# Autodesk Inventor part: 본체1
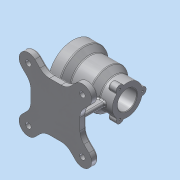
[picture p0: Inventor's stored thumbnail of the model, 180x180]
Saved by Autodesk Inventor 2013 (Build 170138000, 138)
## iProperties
Created: 2017-03
Part Number: 본체1
Material: 알루미늄 6061
Document SubType Name: Modeling
Designer: dgall
Density: 2.71 g/cm^3
Mass: 1008.06 g
Surface Area: 842.101 cm^2
Volume: 371.979 cm^3
Author: dgall
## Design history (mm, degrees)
sketch "스케치1"
  geometry: L1 (0, 0)-(100, 0); L2 (0, 0)-(0, 45); L3 (0, 45)-(20, 45); L4 (20, 45)-(31, 36); L5 (31, 36)-(65, 36); L6 (77, 27.5)-(100, 27.5); L7 (100, 27.5)-(100, 0); L8 (77, 27.5)-(65, 36)
  constraints: 16 end point, 2 perpendicular, 1 horizontal, 1 parallel, 1 vertical
  dimensions: "d0" = 100 distance of L1.start L1.end; "d1" = 20 distance of L2.end L3.end; "d2" = 31 distance from line of L4.end L2; "d5" = 65 distance from line of L2 L5.end; "d6" = 90 diameter of L3 L1; "d7" = 55 diameter of L6 L1; "d8" = 72 diameter of L4.end L1; "d146" = 23 distance from line of L6.start L7
revolve "회전1" sketch "스케치1" stored, may be unused: angle "d10" = 90 deg
node "작업축1"
node "작업 평면2"
  node "작업 평면1"
sketch "스케치2"
  geometry: L1 (6.5, -45)-(-83.5, -45); L2 (-83.5, -45)-(-83.5, 45); L3 (-83.5, 45)-(6.5, 45); L4 (6.5, 45)-(6.5, -45); L5 (6.5, -45)-(-83.5, 45); L6 (-83.5, -45)-(6.5, 45); L7 (-88.5, -45)-(-88.5, 45) reference; L8 (11.5, -27.5)-(11.5, 27.5) reference; 4 further points
  constraints: 12 end point, 4 midpoint, 2 parallel, 1 horizontal, 1 horizontal alignment, 1 perpendicular
  dimensions: "d13" = 90 distance of L2.end L3.end; "d14" = 90 distance of L1.end L2.end; "d15" = 50 distance from line of point (-38.5, 0) L8
extrude "돌출1" join sketch "스케치2" distance "d25" = 12; taper "d26" = 0 deg
sketch "스케치3"
  geometry: L1 (6.5, -45)-(-83.5, -45) reference; L2 (6.5, 45)-(6.5, -45) reference; L3 (-83.5, 45)-(6.5, 45) reference; L4 (-83.5, -45)-(-83.5, 45) reference; L5 (-38.5, 45)-(-38.5, -45); L6 (-83.5, 0)-(6.5, 0); L7 (-87.997, 49.497)-(10.997, -49.497); L8 (10.997, 49.497)-(-87.997, -49.497); L9 (-100.018, 37.477)-(-83.5, 20.958); L10 (-75.977, 61.518)-(-59.458, 45); L11 (23.018, -37.477)-(6.5, -20.958); L12 (-1.023, -61.518)-(-17.542, -45); L13 (23.018, 37.477)-(6.5, 20.958); L14 (-1.023, 61.518)-(-17.542, 45); L15 (-100.018, -37.477)-(-83.5, -20.958); L16 (-75.977, -61.518)-(-59.458, -45); A1 r 17 centre (-87.997, 49.497) between (-100.018, 37.477) and (-75.977, 61.518); A2 r 17 centre (10.997, 49.497) between (23.018, 37.477) and (-1.023, 61.518); A3 r 17 centre (-87.997, -49.497) between (-100.018, -37.477) and (-75.977, -61.518); A4 r 17 centre (10.997, -49.497) between (23.018, -37.477) and (-1.023, -61.518); 7 further points
  constraints: 24 end point, 10 midpoint, 8 point on circle, 8 point on line, 8 tangent, 6 equal length, 4 centre point, 4 horizontal alignment, 4 perpendicular, 2 coincident, 2 vertical alignment, 1 equal radius
  dimensions: "d38" = 70 distance of point (-38.5, 0) L7.start; "d39" = 45 deg angle of L5 L7; "d40" = 34 diameter of A2; "d41" = 34 diameter of A4; "d42" = 34 diameter of A3; "d43" = 70 distance of point (-38.5, 0) L7.end
extrude "돌출2" join sketch "스케치3" distance "d44" = 12; taper "d45" = 0 deg
node "작업 평면3"
sketch "스케치4"
  geometry: L1 (-75.977, -70)-(-104.997, -70) reference; L2 (11.5, -27.5)-(11.5, 27.5) reference; L3 (-88.5, -45)-(-88.5, 45) reference; L4 (-59.458, -70)-(-75.977, -70) reference; L5 (-17.542, -70)-(-59.458, -70) reference; L6 (-1.023, -70)-(-17.542, -70) reference; L7 (6.5, -70)-(23.018, -70) reference; L8 (27.997, -70)-(-1.023, -70) reference; L9 (-75.5, -70)-(-75.5, -3.971); L10 (-75.5, -3.971)-(-1.5, -3.971); L11 (-1.5, -3.971)-(-1.5, -70); L12 (-75.5, -70)-(-1.5, -70); 4 further points
  constraints: 8 end point, 4 perpendicular, 3 midpoint, 2 point on line, 1 coincident, 1 vertical alignment
  dimensions: "d52" = 74 distance of L9.end L10.end; "d55" = 66.02908 distance between parallel lines of L5 L10
extrude "돌출3" join sketch "스케치4" stored distance "d56" = 8; taper "d57" = 0 deg
node "작업 평면4"
sketch "스케치5"
  geometry: L1 (20.958, -82)-(37.477, -82) reference; L2 (20.958, -70)-(20.958, -82) reference; L3 (37.477, -70)-(20.958, -70) reference; L4 (37.477, -82)-(37.477, -70) reference; L5 (-4, -44.822)-(-4, -35.777) reference; L6 (4, -35.777)-(4, -44.822) reference; L7 (-13.944, -7.299)-(-25, -70); L8 (-25, -70)-(25, -70); L9 (25, -70)-(13.944, -7.299); L10 (13.944, -7.299)-(-13.944, -7.299); L11 (-20.958, -70)-(-37.477, -70) reference; A1 r 45 centre (0, 0) between (4, -44.822) and (-4, -44.822) reference; A2 r 36 centre (0, 0) between (4, -35.777) and (-4, -35.777) reference; A3 r 45 centre (0, 0) between (4, -44.822) and (-4, -44.822) reference; 3 further points
  constraints: 8 end point, 2 midpoint, 2 vertical alignment, 1 horizontal alignment, 1 parallel, 1 perpendicular
  dimensions: "d62" = 50 distance of L8.end L7.end; "d64" = 62.70114 distance between parallel lines of L8 L10; "d65" = 100 deg angle of L9 L3
extrude "돌출4" join sketch "스케치5" stored distance "d66" = 8; taper "d67" = 0 deg
sketch "스케치6"
  geometry: L1 (0, 0)-(0, 27.5); L2 (0, 0)-(-23.816, -13.75); L3 (0, 0)-(0, -27.5); L4 (0, 0)-(23.816, -13.75); C1 r 7 at (23.816, -13.75); C2 r 7 at (-23.816, -13.75); C3 r 7 at (0, 27.5); A1 r 27.5 centre (0, 0) between (0, 27.5) and (-23.816, -13.75) reference
  constraints: 8 end point, 4 point on circle, 3 centre point, 3 coincident, 2 equal radius, 1 collinear, 1 vertical
  dimensions: "d71" = 120 deg angle of L1 L2; "d72" = 120 deg angle of L1 L4; "d73" = 14 diameter of C3
extrude "돌출5" join sketch "스케치6" distance "d75" = 15; taper "d76" = 0 deg
sketch "스케치7"
  geometry: L1 (-88.5, -45)-(-88.5, 45) reference; L2 (11.5, -7.292)-(11.5, 26.609) reference; L3 (-88.5, 0)-(11.5, 0); L4 (-88.5, 35)-(-65.5, 35); L5 (-65.5, 35)-(-65.5, 26); L6 (-65.5, 26)-(-18.5, 26); L7 (-18.5, 26)-(-18.5, 17.5); L8 (-18.5, 17.5)-(11.5, 17.5); L9 (-88.5, 35)-(-88.5, 0); L10 (11.5, 17.5)-(11.5, 0); L11 (-108.857, 0)-(31.559, 0) reference
  constraints: 16 end point, 3 parallel, 3 perpendicular, 3 point on line, 2 collinear
  dimensions: "d77" = 35 diameter of L8 L3; "d79" = 52 diameter of L6 L3; "d80" = 70 diameter of L4 L3; "d81" = 23 distance of L4.start L4.end; "d82" = 47 distance of L5.end L6.end
revolve "회전2" sketch "스케치7" stored, may be unused: angle "d83" = 90 deg
node "작업 평면6"
  node "작업 평면5"
sketch "스케치8"
  geometry: L1 (-88.5, -45)-(-88.5, 45) reference; L2 (11.5, 6.943)-(11.5, 27.5) reference; L3 (11.5, 7)-(11.5, -7) reference; L4 (11.5, -27.5)-(11.5, -6.943) reference; C1 r 5 at (-38.5, 0); 4 further points
  constraints: 1 centre point, 1 horizontal alignment, 1 midpoint
  dimensions: "d86" = 50 distance from line of C1.centre L1; "d87" = 10 diameter of C1
extrude "돌출6" join sketch "스케치8" distance "d88" = 13.25; taper "d89" = 0 deg
hole "구멍1" diameter "d92" = 4.134; stored, may be unused: countersink angle "d96" = 90 deg, drill point angle "d98" = 0 deg; dims "d90" = 10, "d91" = 10, "d93" = 6, "d94" = 4, "d95" = 2, "d97" = 8
sketch "스케치9"
  geometry: C1 r 5 at (-87.997, 49.497); C2 r 5 at (10.997, 49.497); C3 r 5 at (10.997, -49.497); C4 r 5 at (-87.997, -49.497); A1 r 17 centre (-87.997, 49.497) between (-75.977, 61.518) and (-100.018, 37.477) reference; A2 r 17 centre (-87.997, -49.497) between (-100.018, -37.477) and (-75.977, -61.518) reference; A3 r 17 centre (10.997, -49.497) between (-1.023, -61.518) and (23.018, -37.477) reference; A4 r 17 centre (10.997, 49.497) between (23.018, 37.477) and (-1.023, 61.518) reference; 1 further point
  constraints: 4 centre point, 4 coincident, 3 equal radius
  dimensions: "d99" = 10 diameter of C1
extrude "돌출7" cut sketch "스케치9" stored distance "d101" = 13.25; taper "d102" = 0 deg
sketch "스케치10"
  geometry: L1 (0, 0)-(0, 40); C1 r 45 at (0, 0) reference; A1 r 40 centre (0, 0) between (0, 40) and (0, 40)
  constraints: 2 end point, 2 point on circle, 1 centre point, 1 coincident, 1 vertical
  dimensions: "d103" = 80 diameter of A1
hole "구멍2" sketch "스케치10" at (0, 40) diameter "d105" = 3.242; stored, may be unused: countersink angle "d109" = 90 deg, drill point angle "d111" = 118 deg; dims "d106" = 9, "d107" = 4, "d108" = 2, "d110" = 11
sketch "스케치11"
  geometry: A1 r 7 centre (-23.816, -41.25) between (-26.516, -34.792) and (-19.573, -46.817) reference; A2 r 7 centre (23.816, -41.25) between (19.573, -46.817) and (26.516, -34.792) reference; A3 r 7 centre (0, 0) between (6.943, -0.891) and (-6.943, -0.891) reference; 3 further points
  constraints: 3 coincident
hole "구멍3" sketch "스케치11" at (0, 0), (23.816, -41.25), (-23.816, -41.25) diameter "d115" = 3.242; stored, may be unused: countersink angle "d119" = 90 deg, drill point angle "d121" = 118 deg; dims "d116" = 9, "d117" = 4, "d118" = 2, "d120" = 11
sketch "스케치12"
  geometry: L1 (-83.5, 20.958)-(-83.5, -20.958) reference; 2 further points
  constraints: 1 other
  dimensions: "d122" = 45 distance from line of point (-38.5, -35) L1; "d123" = 35 vertical distance of point (-38.5, -35) point (-88.5, 0)
feature "엠보싱1" sketch "스케치12" dims "d0" = 100, "d1" = 20, "d2" = 31, "d5" = 65, "d6" = 90, "d7" = 55, "d8" = 72, "d13" = 90, "d14" = 90, "d15" = 50, "d124" = 0.5, "d125" = 0, "d146" = 23
chamfer "모따기1" distance "d126" = 1; stored, may be unused: second distance "d127" = 2, angle "d128" = 45 deg
fillet "모깎기1" dims "d129" = 25
fillet "모깎기2" dims "d130" = 3
fillet "모깎기3" dims "d131" = 3
fillet "모깎기4" dims "d132" = 3
fillet "모깎기5" dims "d133" = 3
fillet "모깎기6" dims "d134" = 3
fillet "모깎기11" dims "d139" = 3
fillet "모깎기12" dims "d140" = 3
fillet "모깎기13" dims "d141" = 3
fillet "모깎기15" dims "d143" = 1
fillet "모깎기16" dims "d144" = 3
fillet "모깎기17" dims "d145" = 1
node "솔리드1"
pattern_circular "원형 패턴1" dims angle "d113" = 360 deg
node "투영된 루프1"
node "투영된 루프2"
other parameters: "d11" = 0, "d12" = -82, "d46" = 0, "d84" = 0
